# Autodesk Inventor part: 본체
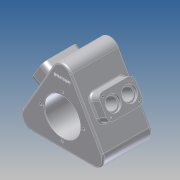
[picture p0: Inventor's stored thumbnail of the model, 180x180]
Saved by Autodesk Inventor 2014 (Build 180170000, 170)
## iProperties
Company: 한국ATC센터
Created: 2014-01
Part Number: 본체
Document SubType Name: Modeling
Designer: KYOUNG IL JANG
Density: 2.71 g/cm^3
Material: 알루미늄 6061
Mass: 3176.1 g
Surface Area: 1165.55 cm^2
Volume: 1171.99 cm^3
Vendor: CBT Solutions
Appearance: 알루미늄 - 평지
Author: KYOUNG IL JANG
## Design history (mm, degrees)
sketch "스케치1"
  geometry: C1 r 75 at (0, 0); C2 r 47.5 at (0, 0); 1 further point
  constraints: 2 centre point, 2 coincident
  dimensions: "d0" = 150 diameter of C1; "d1" = 95 diameter of C2
extrude "돌출1" new body sketch "스케치1" distance "d2" = 95; taper "d3" = 0 deg
node "작업 평면1"
  node "작업 평면3"
sketch "스케치2"
  geometry: L1 (95, 47.5)-(95, -47.5) reference; L2 (0, 47.5)-(0, -47.5) reference; L3 (0, -22.5)-(70, -22.5); L4 (70, -22.5)-(70, 22.5); L5 (70, 22.5)-(0, 22.5); 3 further points
  constraints: 6 end point, 3 perpendicular, 2 midpoint, 2 point on line, 1 horizontal alignment
  dimensions: "d5" = 45 distance of L3.end L4.end; "d104" = 70 distance of L4.end L5.end
extrude "돌출2" join sketch "스케치2" stored distance "d7" = 100; taper "d8" = 0 deg
fillet "모깎기1" dims "d9" = 10
sketch "스케치3"
  geometry: L1 (60.622, -55)-(-60.622, -55); L2 (-77.942, -25)-(-17.321, 80); L3 (17.321, 80)-(77.942, -25); A1 r 20 centre (-60.622, -35) between (-77.942, -25) and (-60.622, -55); A2 r 20 centre (0, 70) between (17.321, 80) and (-17.321, 80); A3 r 20 centre (60.622, -35) between (60.622, -55) and (77.942, -25); 5 further points
  constraints: 6 end point, 6 point on circle, 6 point on line, 6 tangent, 3 centre point, 2 equal radius, 1 coincident, 1 horizontal, 7 other
  dimensions: "d14" = 20 radius of A1; "d15" = 55 distance from line of L2 point (0, 0)
extrude "돌출3" join sketch "스케치3" distance "d16" = 15; taper "d17" = 0 deg
extrude "돌출9" join sketch "스케치3" distance "d100" = 80; taper "d101" = 0 deg
fillet "모깎기3" dims "d19" = 3
sketch "스케치4"
  geometry: C1 r 47.5 at (0, 0) reference; C2 r 32.5 at (0, 0); 1 further point
  constraints: 1 centre point, 1 coincident
  dimensions: "d20" = 65 diameter of C2
extrude "돌출4" cut sketch "스케치4" distance "d21" = 15; taper "d22" = 0 deg
fillet "모깎기4" dims "d23" = 3
sketch "스케치5"
  geometry: C1 r 35 at (0, 0); 1 further point
  constraints: 1 centre point, 1 coincident
  dimensions: "d25" = 70 diameter of C1
extrude "돌출5" cut sketch "스케치5" distance "d26" = 85; taper "d27" = 0 deg
sketch "스케치6"
  geometry: L1 (0, 12.5)-(0, -12.5) reference; 3 further points
  constraints: 2 horizontal alignment, 1 midpoint
  dimensions: "d108" = 20 distance from line of point (20, 0) L1; "d109" = 32 distance of point (52, 0) point (20, 0)
hole "구멍1" sketch "스케치6" at (20, 0), (52, 0) diameter "d30" = 22; stored, may be unused: countersink angle "d34" = 90 deg, drill point angle "d36" = 118 deg; dims "d31" = 6, "d32" = 28, "d33" = 5, "d35" = 8
node "작업 평면2"
sketch "스케치8"
  geometry: C1 r 18.5 at (0, 0); 1 further point
  constraints: 1 centre point, 1 coincident
  dimensions: "d44" = 37 diameter of C1
extrude "돌출7" cut sketch "스케치8" distance "d45" = 17; taper "d46" = 0 deg
sketch "스케치9"
  geometry: C1 r 13 at (0, 0); 1 further point
  constraints: 1 centre point, 1 coincident
  dimensions: "d47" = 26 diameter of C1
extrude "돌출8" cut sketch "스케치9" distance "d48" = 2; taper "d49" = 0 deg
fillet "모깎기6" dims "d50" = 3, "d51" = 0.3
chamfer "모따기1" distance "d52" = 1; stored, may be unused: second distance "d53" = 2, angle "d54" = 45 deg
sketch "스케치10"
  geometry: L1 (0, 12.5)-(0, -12.5) reference; A1 r 10 centre (60, -12.5) between (60, -22.5) and (70, -12.5) reference; 5 further points
  constraints: 2 horizontal alignment, 2 vertical alignment
  dimensions: "d58" = 7.5 distance from line of point (7.5, -16) L1; "d105" = 56 distance of point (7.5, -16) point (63.5, -16); "d106" = 32 distance of point (7.5, -16) point (7.5, 16); "d107" = 16 vertical distance of point (0, 0) point (7.5, -16) (= 0.5 x d106)
hole "구멍2" sketch "스케치10" at (7.5, -16), (63.5, -16), (63.5, 16), (7.5, 16) diameter "d59" = 3.242; stored, may be unused: countersink angle "d63" = 90 deg, drill point angle "d65" = 118 deg; dims "d60" = 10, "d61" = 4, "d62" = 2, "d64" = 13
sketch "스케치11" dims "d1" = 95
  geometry: C1 r 3.3 at (0, 42); C2 r 3.3 at (-34.641, -20) reference; C3 r 3.3 at (34.641, -20) reference; 1 further point
  constraints: 1 centre point, 1 vertical alignment
  dimensions: "d96" = 42 distance of point (0, 0) C1.centre
hole "구멍3" sketch "스케치11" at (0, 42) diameter "d72" = 5.242; stored, may be unused: countersink angle "d76" = 90 deg, drill point angle "d78" = 118 deg; dims "d73" = 12, "d74" = 4, "d75" = 2, "d77" = 15
chamfer "모따기2" distance "d93" = 1; stored, may be unused: second distance "d94" = 2, angle "d95" = 45 deg
sketch "스케치14"
  geometry: C1 r 36 at (0, 0) reference; 1 further point
  constraints: 1 vertical alignment, 1 other
  dimensions: "d110" = 65 distance of C1.centre point (0, 65)
feature "엠보싱2" sketch "스케치14" dims "d0" = 150, "d1" = 95, "d14" = 20, "d15" = 55, "d98" = 0.5, "d99" = 0
node "솔리드1"
pattern_circular "원형 패턴1" dims angle "d11" = 120 deg
pattern_circular "원형 패턴4" dims angle "d70" = 120 deg
pattern_circular "원형 패턴3" dims angle "d67" = 360 deg
pattern_circular "원형 패턴5" dims angle "d80" = 360 deg
node "투영된 루프1"
node "투영된 루프2"
node "참조2"
node "참조3"
other parameters: "d102" = 120 deg, "d103" = -75
